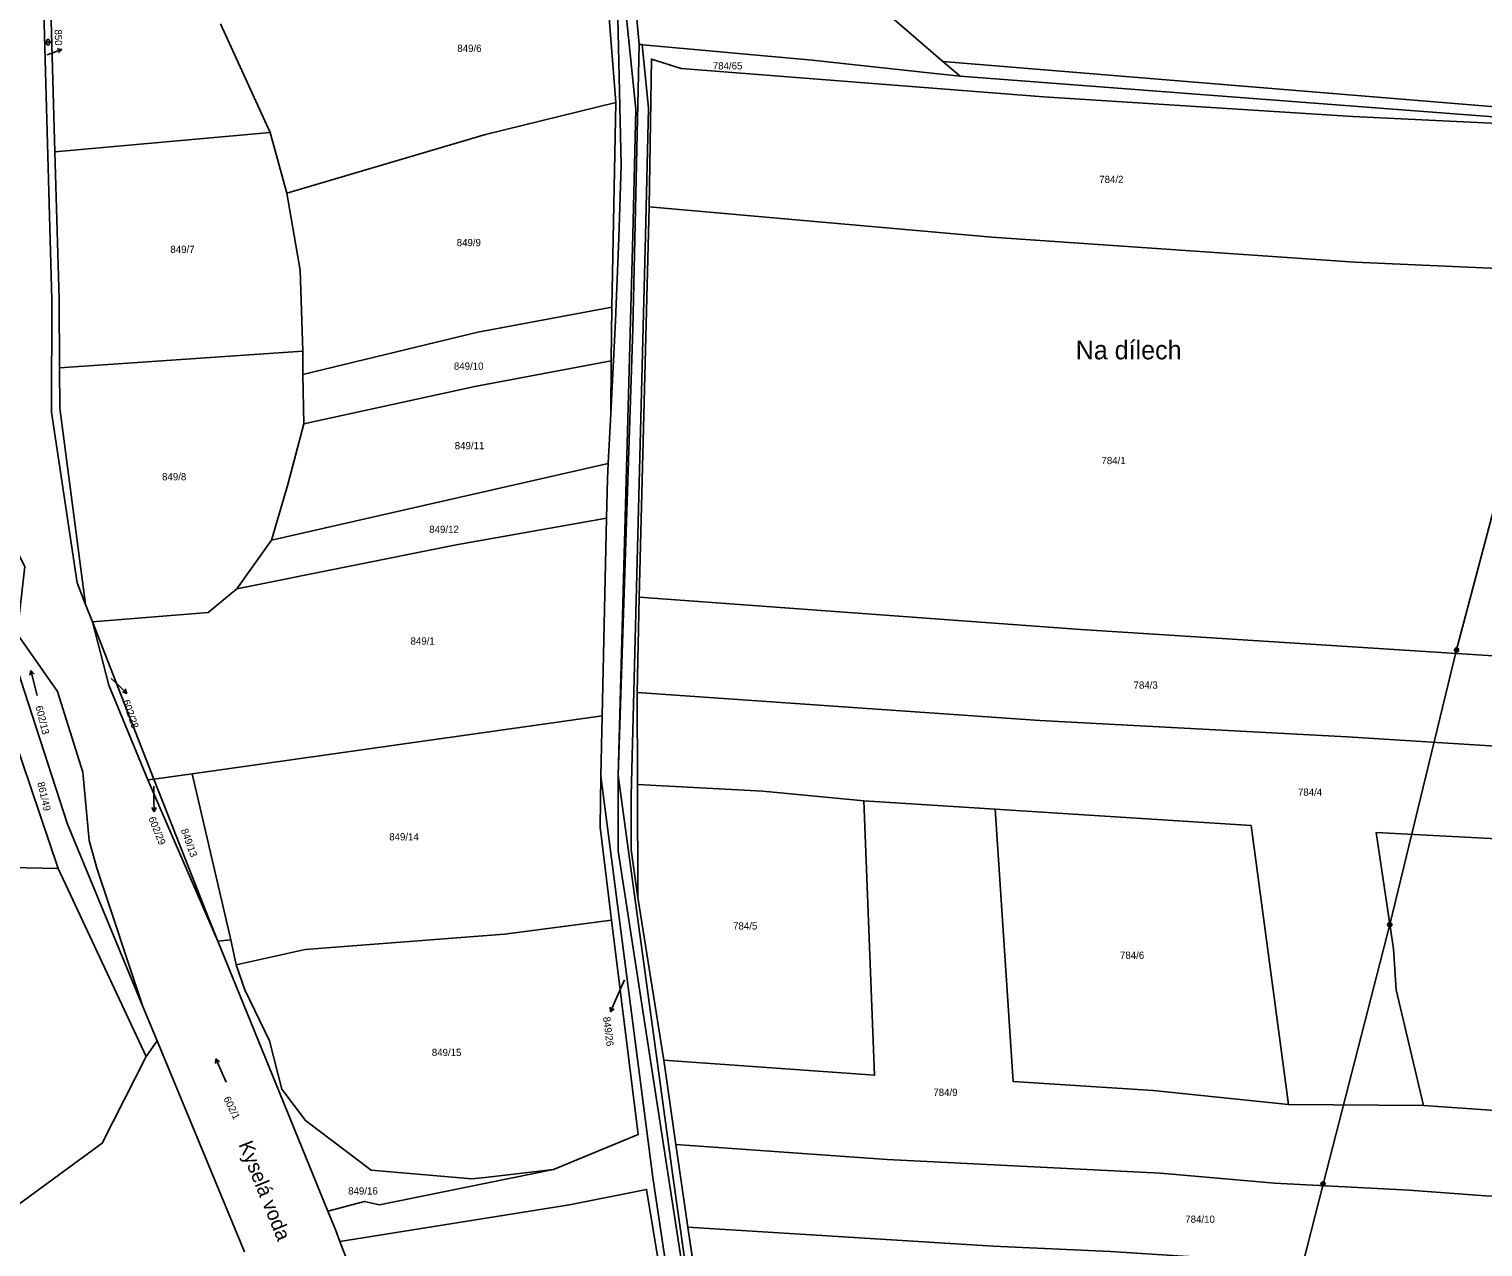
# Model space of a CAD drawing. Extents: x -757266 to -753360, y -1162585 to -1157740.
# Drawn here: x -756866.4 to -756524.8, y -1159849.8 to -1159563.7 of the extents above; entities that cross this region are included whole.
import ezdxf

# ---------------------------------------------------------------- set-up
doc = ezdxf.new("R2010")
doc.units = 0
for name, color, linetype in [('Hranice parcel', 7, 'Continuous'), ('Parcelní čísla', 7, 'Continuous'), ('Pop  PČ popisy', 7, 'Continuous'), ('Poz předměty', 7, 'Continuous'), ('Vnitřní kresba', 7, 'Continuous'), ('Věcná břemena k části', 7, 'Continuous'), ('Značky kultur', 7, 'Continuous')]:
    doc.layers.add(name, color=color, linetype=linetype)

msp = doc.modelspace()

# ---------------------------------------------------------------- linework, layer by layer
at = {"layer": 'Hranice parcel'}
for p, q in [((-756860.32, -1159592.53), (-756862.76, -1159507.3)), ((-756728.56, -1159581), (-756732.09, -1159535.43)), ((-756809.73, -1159588.01), (-756821.38, -1159562.46)), ((-756651.67, -1159571.35), (-756516.91, -1159582.4)), ((-756729.44, -1159629.02), (-756728.56, -1159581)), ((-756860.32, -1159592.53), (-756809.73, -1159588.01)), ((-756809.73, -1159588.01), (-756805.81, -1159602.31)), ((-756720.69, -1159605.49), (-756723.07, -1159697.2)), ((-756729.58, -1159641.64), (-756729.44, -1159629.02)), ((-756859.2, -1159643.28), (-756802.07, -1159639.41)), ((-756802.04, -1159644.9), (-756802.07, -1159639.41)), ((-756729.69, -1159654.04), (-756729.58, -1159641.64)), ((-756801.84, -1159656.48), (-756802.04, -1159644.9)), ((-756729.69, -1159654.04), (-756730.3, -1159665.81)), ((-756809.42, -1159683.76), (-756730.3, -1159665.81)), ((-756730.69, -1159678.64), (-756731.74, -1159725.08)), ((-756817.58, -1159695.21), (-756809.42, -1159683.76)), ((-756723.07, -1159697.2), (-756723.52, -1159719.57)), ((-756851.49, -1159703.02), (-756853.1, -1159698.91)), ((-756837.03, -1159739.93), (-756851.49, -1159703.02)), ((-756723.52, -1159719.57), (-756723.41, -1159741.19)), ((-756828.09, -1159738.67), (-756731.74, -1159725.08)), ((-756731.74, -1159725.08), (-756732.06, -1159739.24)), ((-756838.51, -1159740.14), (-756837.03, -1159739.93)), ((-756822, -1159778.03), (-756838.51, -1159740.14)), ((-756837.03, -1159739.93), (-756828.09, -1159738.67)), ((-756818.98, -1159777.72), (-756828.09, -1159738.67)), ((-756670.27, -1159745.03), (-756639.43, -1159747.02)), ((-756838.83, -1159805.07), (-756859.54, -1159760.95)), ((-756822, -1159778.03), (-756818.98, -1159777.72)), ((-756796.17, -1159841.44), (-756822, -1159778.03)), ((-756818.98, -1159777.72), (-756817.73, -1159783.6)), ((-756839.63, -1159793.32), (-756836.29, -1159801.39)), ((-756838.83, -1159805.07), (-756836.29, -1159801.39)), ((-756836.29, -1159801.39), (-756815.78, -1159850.98)), ((-756717.27, -1159806), (-756714.41, -1159825.76)), ((-756570.48, -1159816.41), (-756538.76, -1159816.62)), ((-756714.41, -1159825.76), (-756711.61, -1159845.21)), ((-756711.61, -1159845.21), (-756705.96, -1159882.87)), ((-756789.91, -1159857.57), (-756793.35, -1159848.53))]:
    msp.add_line(p, q, dxfattribs=at)
for points in [[(-756878.84, -1159410.04), (-756880.4, -1159410.39), (-756864.45, -1159503.19), (-756861.05, -1159627.24), (-756861.08, -1159653.69), (-756855.08, -1159693.86), (-756853.1, -1159698.91)], [(-756721.03, -1159511.46), (-756722.4, -1159516.74), (-756724.7, -1159529.43), (-756724.87, -1159547.42), (-756723.02, -1159567.31)], [(-756721.03, -1159511.46), (-756688.71, -1159539.34), (-756653.94, -1159569.39), (-756651.67, -1159571.35)], [(-756730.02, -1159528.29), (-756729.15, -1159545.86), (-756728.07, -1159561.05), (-756727.24, -1159595.66), (-756727.85, -1159612.75), (-756728.58, -1159632.24), (-756729.69, -1159654.04)], [(-756663.93, -1160134.3), (-756668.06, -1160122.5), (-756695.18, -1159970.34), (-756700.45, -1159936.54), (-756715.15, -1159833.13), (-756727.95, -1159739.12), (-756724.55, -1159634.14), (-756723.02, -1159567.31)], [(-756723.02, -1159567.31), (-756682.38, -1159571.04), (-756653.58, -1159574.18), (-756647.66, -1159574.82), (-756651.67, -1159571.35)], [(-756516.36, -1159586.16), (-756555.4, -1159584.25), (-756628.04, -1159579.63), (-756713.21, -1159573.01), (-756720.17, -1159570.79), (-756720.69, -1159605.49)], [(-756805.81, -1159602.31), (-756759.15, -1159588.5), (-756728.56, -1159581)], [(-756859.2, -1159643.28), (-756859.33, -1159627.19), (-756860.32, -1159592.53)], [(-756802.07, -1159639.41), (-756802.65, -1159620.38), (-756805.81, -1159602.31)], [(-756510.66, -1159620.46), (-756554.92, -1159618.45), (-756640.19, -1159612.61), (-756720.69, -1159605.49)], [(-756802.04, -1159644.9), (-756760.91, -1159634.92), (-756729.44, -1159629.02)], [(-756801.84, -1159656.48), (-756761.68, -1159647.7), (-756729.58, -1159641.64)], [(-756853.1, -1159698.91), (-756859.13, -1159652.75), (-756859.2, -1159643.28)], [(-756809.42, -1159683.76), (-756805.55, -1159670.72), (-756801.84, -1159656.48)], [(-756730.3, -1159665.81), (-756730.48, -1159669.39), (-756730.69, -1159678.64)], [(-756879.37, -1159666.71), (-756867.38, -1159689.96), (-756869.15, -1159705.8), (-756859.68, -1159719.37), (-756853.75, -1159738.29), (-756852.27, -1159754.38), (-756850.44, -1159760.89), (-756839.63, -1159793.32)], [(-756730.69, -1159678.64), (-756766.02, -1159684.89), (-756817.58, -1159695.21)], [(-756878.48, -1159685.53), (-756857.34, -1159750.5), (-756839.63, -1159793.32)], [(-756817.58, -1159695.21), (-756824.27, -1159700.82), (-756851.49, -1159703.02)], [(-756723.07, -1159697.2), (-756619.28, -1159704.79), (-756495.4, -1159712.69)], [(-756838.51, -1159740.14), (-756847.6, -1159717.89), (-756851.49, -1159703.02)], [(-756859.54, -1159760.95), (-756870.08, -1159729.58), (-756874.71, -1159706.71)], [(-756723.52, -1159719.57), (-756628.94, -1159726.15), (-756556.68, -1159730.01), (-756491.97, -1159734.04)], [(-756859.54, -1159760.95), (-756892.97, -1159760.25), (-756902.43, -1159749.68), (-756910.67, -1159737.76)], [(-756822, -1159778.03), (-756824.71, -1159771.37), (-756837.03, -1159739.93)], [(-756729.55, -1159773.1), (-756732.19, -1159751.21), (-756732.06, -1159739.24)], [(-756732.06, -1159739.24), (-756719.8, -1159833.57), (-756706, -1159926.11)], [(-756723.41, -1159741.19), (-756693.99, -1159742.76), (-756670.27, -1159745.03)], [(-756723.41, -1159741.19), (-756723.35, -1159767.72), (-756717.27, -1159806)], [(-756717.27, -1159806), (-756667.71, -1159809.51), (-756670.27, -1159745.03)], [(-756639.43, -1159747.02), (-756579.22, -1159750.86), (-756570.48, -1159816.41)], [(-756639.43, -1159747.02), (-756635.19, -1159810.95), (-756602.25, -1159813.1), (-756570.48, -1159816.41)], [(-756538.76, -1159816.62), (-756545.21, -1159789.46), (-756545.83, -1159779.78), (-756549.89, -1159752.51), (-756520.03, -1159754.04), (-756504.84, -1159755.14)], [(-756817.73, -1159783.6), (-756801.53, -1159779.97), (-756754.71, -1159776.34), (-756729.55, -1159773.1)], [(-756743.19, -1159831.65), (-756723.24, -1159823.45), (-756729.55, -1159773.1)], [(-756817.73, -1159783.6), (-756815.7, -1159789.46), (-756809.87, -1159801.4), (-756806.96, -1159812.79), (-756801.4, -1159820.17), (-756786.01, -1159831.83), (-756762.33, -1159833.84), (-756759.22, -1159833.56), (-756743.19, -1159831.65)], [(-756888, -1159853.83), (-756849.21, -1159825.49), (-756838.83, -1159805.07)], [(-756538.76, -1159816.62), (-756507.32, -1159818.8), (-756500.38, -1159820.47), (-756492.35, -1159820.41)], [(-756714.41, -1159825.76), (-756664.75, -1159829.27), (-756600.59, -1159832.53), (-756573.76, -1159834.87), (-756542.15, -1159836.48), (-756524.17, -1159837.83), (-756470.09, -1159840.31)], [(-756796.17, -1159841.44), (-756787.55, -1159839.16), (-756784.04, -1159839.94), (-756743.19, -1159831.65)], [(-756713.32, -1159884.66), (-756721.28, -1159836.33), (-756739.4, -1159839.97), (-756793.35, -1159848.53)], [(-756793.35, -1159848.53), (-756794.32, -1159845.98), (-756796.17, -1159841.44)], [(-756711.61, -1159845.21), (-756639.86, -1159849.64), (-756612.34, -1159850.89), (-756541.61, -1159855.49), (-756465.31, -1159859.79)]]:
    msp.add_lwpolyline(points, dxfattribs=at)
at = {"layer": 'Pop  PČ popisy'}
for p, q in [((-756862.13, -1159569.76), (-756861.5, -1159569.53)), ((-756861.5, -1159569.53), (-756858.68, -1159568.504)), ((-756858.68, -1159568.504), (-756859.792, -1159568.376)), ((-756858.68, -1159568.504), (-756859.45, -1159569.317)), ((-756847.06, -1159716.26), (-756845.55, -1159717.72)), ((-756845.55, -1159717.72), (-756843.391, -1159719.805)), ((-756843.391, -1159719.805), (-756844.46, -1159719.469)), ((-756843.391, -1159719.805), (-756843.764, -1159718.749)), ((-756837.09, -1159741.59), (-756837.06, -1159744.61)), ((-756837.06, -1159744.61), (-756837.008, -1159747.611)), ((-756837.008, -1159747.611), (-756837.526, -1159746.618)), ((-756837.008, -1159747.611), (-756836.524, -1159746.6)), ((-756726.46, -1159787.12), (-756728.58, -1159791.86)), ((-756728.58, -1159791.86), (-756729.801, -1159794.602)), ((-756729.801, -1159794.602), (-756729.851, -1159793.483)), ((-756729.801, -1159794.602), (-756728.936, -1159793.89))]:
    msp.add_line(p, q, dxfattribs=at)
at = {"layer": 'Poz předměty'}
for p, q in [((-756531, -1159709.58), (-756508.73, -1159625.19)), ((-756546.7, -1159774.11), (-756531, -1159709.58)), ((-756562.37, -1159835.06), (-756546.7, -1159774.11)), ((-756580.94, -1159908.15), (-756562.37, -1159835.06))]:
    msp.add_line(p, q, dxfattribs=at)
for centre, radius in [((-756531.0034, -1159709.5799), 0.5), ((-756531.0034, -1159709.5799), 0.4), ((-756531.0034, -1159709.5799), 0.3), ((-756531.0034, -1159709.5799), 0.2), ((-756531.0034, -1159709.5799), 0.1), ((-756546.7034, -1159774.1099), 0.5), ((-756546.7034, -1159774.1099), 0.4), ((-756546.7034, -1159774.1099), 0.3), ((-756546.7034, -1159774.1099), 0.2), ((-756546.7034, -1159774.1099), 0.1), ((-756562.3734, -1159835.0599), 0.5), ((-756562.3734, -1159835.0599), 0.4), ((-756562.3734, -1159835.0599), 0.3), ((-756562.3734, -1159835.0599), 0.2), ((-756562.3734, -1159835.0599), 0.1)]:
    msp.add_circle(centre, radius, dxfattribs=at)
at = {"layer": 'Vnitřní kresba'}
msp.add_line((-756647.66, -1159574.82), (-756516.56, -1159584.76), dxfattribs=at)
at = {"layer": 'Věcná břemena k části'}
for points in [[(-756727.87, -1159542.7), (-756723.85, -1159582.52), (-756724.53, -1159612.07), (-756727.95, -1159739.12), (-756727.95, -1159756.77), (-756717.19, -1159826.84), (-756712.25, -1159858.83), (-756705.53, -1159909.84), (-756700.23, -1159945.5), (-756677.54, -1160079.21), (-756675.52, -1160080.63), (-756671.77, -1160083.27), (-756626.8, -1160106.11), (-756624.47, -1160107.3), (-756623.41, -1160107.69), (-756620.5, -1160109.46), (-756616.66, -1160111.27), (-756599.25, -1160119.99), (-756595.04, -1160121.46), (-756493.75, -1160157.9)], [(-756721.54, -1159612.28), (-756720.87, -1159582.32), (-756722.37, -1159567.37), (-756723.02, -1159567.31), (-756724.87, -1159547.42)], [(-756492.61, -1160155.11), (-756594.02, -1160118.62), (-756598.14, -1160117.18), (-756615.35, -1160108.56), (-756625.46, -1160103.42), (-756670.22, -1160080.69), (-756674.8, -1160077.47), (-756697.3, -1159944.99), (-756702.56, -1159909.44), (-756703.3, -1159901.91), (-756704.83, -1159892.26), (-756705.96, -1159882.87), (-756711.61, -1159845.21), (-756714.41, -1159825.76), (-756717.27, -1159806), (-756723.35, -1159767.72), (-756724.95, -1159756.57), (-756724.88, -1159743.81), (-756721.54, -1159612.28)]]:
    msp.add_lwpolyline(points, dxfattribs=at)
at = {"layer": 'Značky kultur'}
for p, q in [((-756862.581, -1159566.801), (-756861.239, -1159566.801)), ((-756862.245, -1159566.465), (-756862.245, -1159567.136)), ((-756861.575, -1159567.136), (-756861.575, -1159566.465)), ((-756865.932, -1159714.45), (-756866.182, -1159715.52)), ((-756864.48, -1159720.272), (-756865.932, -1159714.45)), ((-756865.932, -1159714.45), (-756865.209, -1159715.277)), ((-756822.499, -1159805.66), (-756822.56, -1159806.757)), ((-756820.059, -1159811.141), (-756822.499, -1159805.66)), ((-756822.499, -1159805.66), (-756821.644, -1159806.349))]:
    msp.add_line(p, q, dxfattribs=at)
for centre, start, end in [((-756861.91, -1159566.4656), 0, 180), ((-756861.91, -1159567.1356), 180, 359.987886)]:
    msp.add_arc(centre, 0.335, start, end, dxfattribs=at)

# ---------------------------------------------------------------- texts
at = {"layer": 'Parcelní čísla'}
for s, rotation, p in [('850', 271, (-756860.358, -1159563.819)), ('602/28', 289, (-756844.423, -1159721.627)), ('602/13', 284, (-756864.884, -1159722.875)), ('861/49', 283, (-756864.448, -1159740.791)), ('602/29', 292, (-756838.369, -1159749.136)), ('849/13', 290, (-756830.748, -1159751.9)), ('849/26', 277, (-756731.529, -1159795.87)), ('602/1', 296, (-756820.743, -1159814.982))]:
    msp.add_text(s, height=1.7, rotation=rotation, dxfattribs=at).set_placement(p)
for s, p in [('849/6', (-756765.76, -1159569.1)), ('784/65', (-756705.74, -1159573.21)), ('784/2', (-756614.95, -1159599.88)), ('849/7', (-756833.18, -1159616.32)), ('849/9', (-756765.91, -1159614.73)), ('849/10', (-756766.57, -1159643.76)), ('849/11', (-756766.37, -1159662.44)), ('784/1', (-756614.43, -1159665.94)), ('849/8', (-756835.13, -1159669.74)), ('849/12', (-756772.36, -1159682.12)), ('849/1', (-756776.75, -1159708.34)), ('784/3', (-756606.88, -1159718.7)), ('784/4', (-756568.26, -1159743.85)), ('849/14', (-756781.76, -1159754.34)), ('784/5', (-756700.97, -1159775.27)), ('784/6', (-756610.07, -1159782.16)), ('849/15', (-756771.76, -1159805)), ('784/9', (-756653.92, -1159814.37)), ('849/16', (-756791.41, -1159837.53)), ('784/10', (-756594.74, -1159844.18))]:
    msp.add_text(s, height=1.7, dxfattribs=at).set_placement(p)
at = {"layer": 'Pop  PČ popisy'}
msp.add_text('Na dílech', height=4.4, dxfattribs=at).set_placement((-756620.47, -1159641.32))
msp.add_text('Kyselá voda', height=3.399996, rotation=292, dxfattribs=at).set_placement((-756817.196, -1159825.746))

doc.saveas('drawing.dxf')
